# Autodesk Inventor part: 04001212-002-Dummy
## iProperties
Shininess: 20.0
Length Units: 11269
Angle Units: 11279
Time Units: 11290
Mass Units: 11283
Length Display Precision: 3
Angle Display Precision: 2
Compacted: True
Created: 2004-04
Part Number: 04001212-002-Dummy
Material: Standard
Document SubType Name: Blech
Designer: Pfeiffer A.
Cost Center: 2 kg
Authority: 1972497,86 mm^3
Manufacturer: Standard
Standards Organization: Custom
Density: 0.0
Volumn: 0.0
Area: 0.0
PropertySet Name: Model Information
Control State: 0
Master: False
Checked Out: False
Objekthöhe: 0,500 mm
SaveDate: 2004-04-15
SaveTime: 13:56
TotalMass: 2 kg
TotalVolume: 1972497,86 mm^3
SM_Thickness: 0,5 mm
SM_Style: Norm
SM_Extents: N/A
Author: Pfeiffer A.
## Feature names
1. Extrusion1
2. Extrusion2
3. Extrusion3
4. Rundung4 [Fillet]
5. Rundung5 [Fillet]
6. Extrusion5
7. Extrusion6
8. Wandstärke2
9. Biegung1
10. Biegung2
